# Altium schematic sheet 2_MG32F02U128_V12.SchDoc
size 388 x 266 mm; PageSetup: Record=PageOptions|CenterHorizontal=True|CenterVertical=True|PrintScale=0.73|XCorrection=1.00|YCorrection=1.00|PrintKind=1|BorderSize=5000000|LeftOffset=0|BottomOffset=0|Orientation=2|PaperLength=1000|PaperWidth=1000|Scale=100|PaperSource=7|PrintQuality=-4|MediaType=1|DitherType=10|PaperKind=A4 (210 x 297 mm)|PrintScaleMode=1
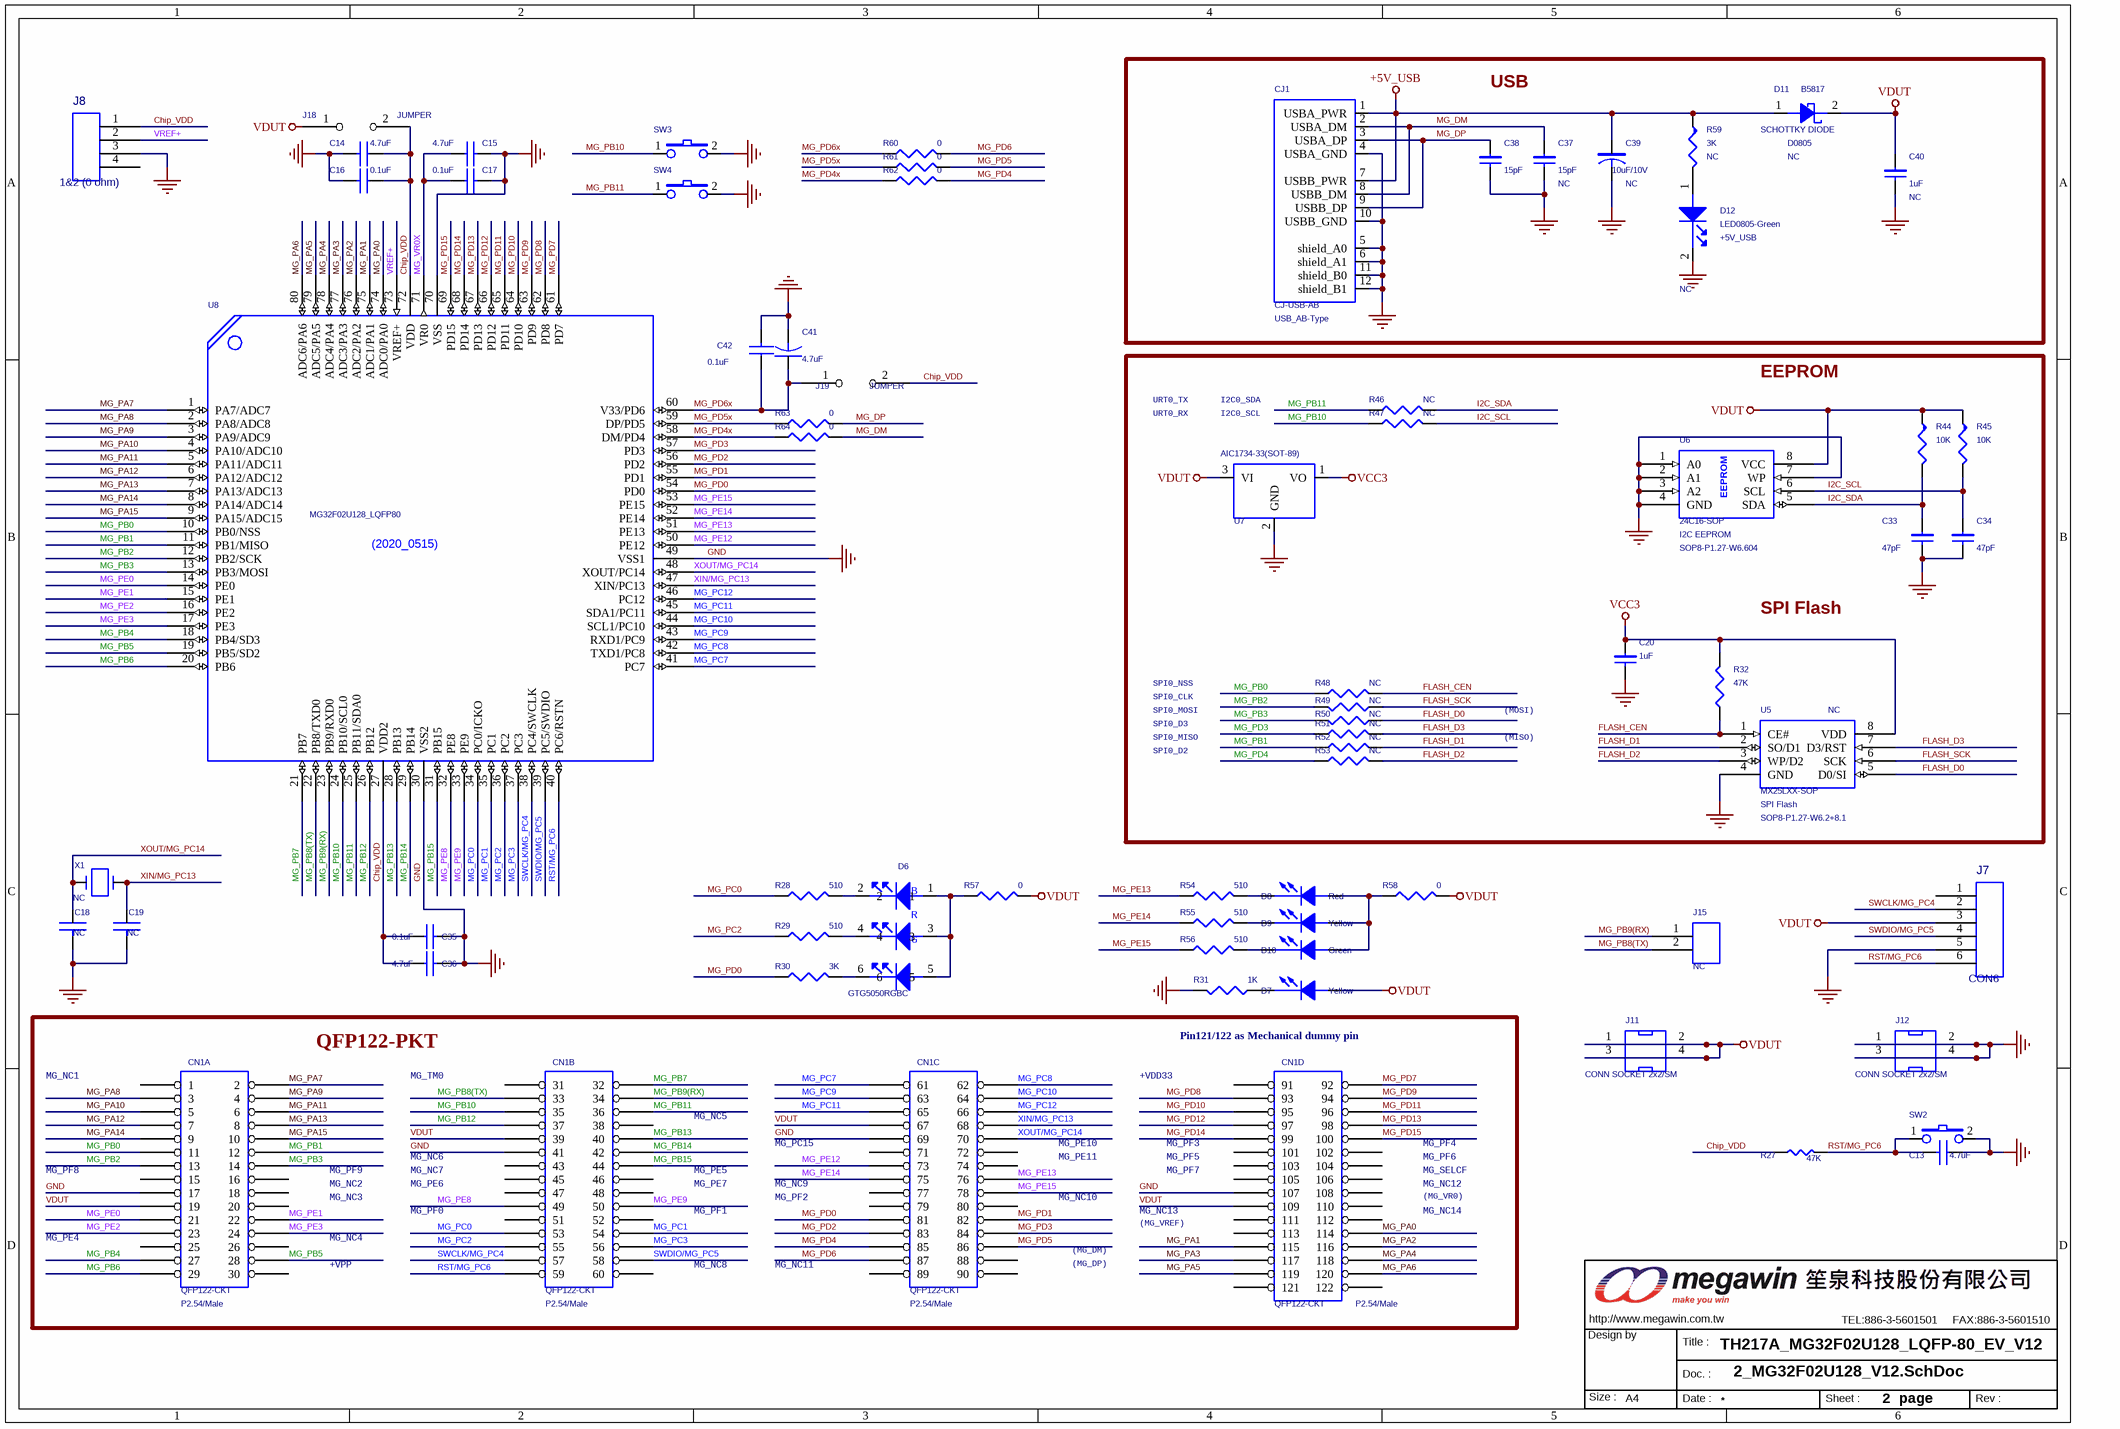
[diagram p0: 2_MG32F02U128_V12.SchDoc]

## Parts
C13  4.7uF  [0805C]
C14  4.7uF  [0805C]
C15  4.7uF  [0805C]
C16  0.1uF  [0603C]
C17  0.1uF  [0603C]
C18  NC  [0603C]
C19  NC  [0603C]
C20  1uF  [0603C]
C33  47pF  [0603C]
C34  47pF  [0603C]
C35  0.1uF  [0603C]
C36  4.7uF  [0805C]
C37  15pF  Assembly: NC  [0603C]
C38  15pF  [0603C]
C39  10uF/10V  Assembly: NC  [0805C]
C40  1uF  Assembly: NC  [0603C]
C41  4.7uF  [0805C]
C42  0.1uF  [0603C]
CJ1  CJ-USB-AB  Package: USB_AB-Type  [CON_USB-AB]
CN1  QFP122-CKT  Package: P2.54/Male  [QFP122-P2.54-CKT]  (parts A,B,C,D of 4)
D6  GTG5050RGBC  [LED6P_RGB_SMD_50X50]
D7  Yellow  [0805D]
D8  Red  [LED38+0805]
D9  Yellow  [LED38+0805]
D10  Green  [LED38+0805]
D11  B5817  Package: D0805  Function: SCHOTTKY DIODE  Assembly: NC  [D5817_SMD_1]
D12  LED0805-Green  Assembly: NC  Function: +5V_USB  [LED-0805]
J7  CON6  [PS6P254]
J8  1&2 (0 ohm)  [PS4P254]
J11  CONN SOCKET 2x2/SM  [PS2X2P254]
J12  CONN SOCKET 2x2/SM  [PS2X2P254]
J15  NC  [PS2P254]
J18  JUMPER  [PS2P254]
J19  JUMPER  [PS2P254]
MW1  OrgAddr3: TEL:886-3-5601501     FAX:886-3-5601510  [MEGAWIN_3.4]  (hidden comment: MW-A4)  (graphical)
R27  47K  [0603R]
R28  510  [0603R]
R29  510  [0603R]
R30  3K  [0603R]
R31  1K  [0603R]
R32  47K  [0603R]
R44  10K  [0603R]
R45  10K  [0603R]
R46  NC  [PS2p254+0603]
R47  NC  [PS2p254+0603]
R48  NC  [PS2p254+0603]
R49  NC  [PS2p254+0603]
R50  NC  [PS2p254+0603]
R51  NC  [PS2p254+0603]
R52  NC  [PS2p254+0603]
R53  NC  [PS2p254+0603]
R54  510  [0603R]
R55  510  [0603R]
R56  510  [0603R]
R57  0  [PS2p254+0603]
R58  0  [PS2p254+0603]
R59  3K  Assembly: NC  [0603R]
R60  0  [0603R]
R61  0  [0603R]
R62  0  [0603R]
R63  0  [0603R]
R64  0  [0603R]
SW2  SW TACT-SPST  [SW_T_2P]  (value not drawn)
SW3  SW TACT-SPST  [SW_T_2P]  (value not drawn)
SW4  SW TACT-SPST  [SW_T_2P]  (value not drawn)
U5  MX25LXX-SOP  Function: SPI Flash  Assembly: NC  Package: SOP8-P1.27-W6.2+8.1  [SO8_208P127]
U6  24C16-SOP  Function: I2C EEPROM  Package: SOP8-P1.27-W6.604  [SO8_150P127]
U7  AIC1734-33(SOT-89)  [SOT89]
U8  MG32F02U128_LQFP80  [QFP80-P0.4-Z12X12]
X1  NC  [X49U]

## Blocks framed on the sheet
USB: C37-C40 CJ1 D11 D12 R59
QFP122-PKT: CN1

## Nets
+5V_USB: C39.1 CJ1.1(USBA_PWR) CJ1.7(USBB_PWR) D11.1(ANODE) R59.1
GND: C13.1 C14.2 C15.2 C16.2 C17.2 C18.2 C19.2 C20.2 C33.2 C34.2 C35.2 C36.2 C37.2 C38.2 C39.2 C40.2 C41.2 C42.2 CJ1.4(USBA_GND) CJ1.5(shield_A0) CJ1.6(shield_A1) CJ1.10(USBB_GND) CJ1.11(shield_B0) CJ1.12(shield_B1) CN1.17 CN1.41 CN1.69 CN1.107 D12.2(C) J7.5 J8.3 J12.1 J12.2 J12.3 J12.4 R31.1 SW2.2 SW3.2 SW4.2 U5.4(GND) U6.1(A0) U6.2(A1) U6.3(A2) U6.4(GND) U6.7(WP) U7.2(GND) U8.30(VSS2) U8.49(VSS1) U8.70(VSS)  [also labelled GND_POWER]
VCC3: C20.1 R32.2 U5.8(VDD) U7.1(VO)
VDUT: C40.1 CN1.19 CN1.39 CN1.67 CN1.109 D7.1(ANODE) D11.2(CATHODE) J7.3 J11.1 J11.2 J11.3 J11.4 J18.1 R44.1 R45.1 R57.2 R58.2 U6.8(VCC) U7.3(VI)
Chip_VDD: C14.1 C16.1 C35.1 C36.1 J8.1 J18.2 J19.2 R27.1 U8.27(VDD2) U8.72(VDD)
FLASH_CEN: R32.1 R48.2 U5.1(CE#)
FLASH_D0: R50.1 U5.5(D0/SI)
FLASH_D1: R52.2 U5.2(SO/D1)
FLASH_D2: R53.2 U5.3(WP/D2)
FLASH_D3: R51.2 U5.7(D3/RST)
FLASH_SCK: R49.1 U5.6(SCK)
I2C_SCL: C34.1 R45.2 R47.2 U6.6(SCL)
I2C_SDA: C33.1 R44.2 R46.2 U6.5(SDA)
MG_DM: C37.1 CJ1.2(USBA_DM) CJ1.8(USBB_DM) R64.2
MG_DP: C38.1 CJ1.3(USBA_DP) CJ1.9(USBB_DP) R63.2
MG_PA0: CN1.114 U8.74(ADC0/PA0)
MG_PA1: CN1.115 U8.75(ADC1/PA1)
MG_PA2: CN1.116 U8.76(ADC2/PA2)
MG_PA3: CN1.117 U8.77(ADC3/PA3)
MG_PA4: CN1.118 U8.78(ADC4/PA4)
MG_PA5: CN1.119 U8.79(ADC5/PA5)
MG_PA6: CN1.120 U8.80(ADC6/PA6)
MG_PA7: CN1.2 U8.1(PA7/ADC7)
MG_PA8: CN1.3 U8.2(PA8/ADC8)
MG_PA9: CN1.4 U8.3(PA9/ADC9)
MG_PA10: CN1.5 U8.4(PA10/ADC10)
MG_PA11: CN1.6 U8.5(PA11/ADC11)
MG_PA12: CN1.7 U8.6(PA12/ADC12)
MG_PA13: CN1.8 U8.7(PA13/ADC13)
MG_PA14: CN1.9 U8.8(PA14/ADC14)
MG_PA15: CN1.10 U8.9(PA15/ADC15)
MG_PB0: CN1.11 R48.1 U8.10(PB0/NSS)
MG_PB1: CN1.12 R52.1 U8.11(PB1/MISO)
MG_PB2: CN1.13 R49.2 U8.12(PB2/SCK)
MG_PB3: CN1.14 R50.2 U8.13(PB3/MOSI)
MG_PB4: CN1.27 U8.18(PB4/SD3)
MG_PB5: CN1.28 U8.19(PB5/SD2)
MG_PB6: CN1.29 U8.20(PB6)
MG_PB7: CN1.32 U8.21(PB7)
MG_PB8(TX): CN1.33 J15.2 U8.22(PB8/TXD0)
MG_PB9(RX): CN1.34 J15.1 U8.23(PB9/RXD0)
MG_PB10: CN1.35 R47.1 SW3.1 U8.24(PB10/SCL0)
MG_PB11: CN1.36 R46.1 SW4.1 U8.25(PB11/SDA0)
MG_PB12: CN1.37 U8.26(PB12)
MG_PB13: CN1.40 U8.28(PB13)
MG_PB14: CN1.42 U8.29(PB14)
MG_PB15: CN1.44 U8.31(PB15)
MG_PC0: CN1.53 R28.1 U8.34(PC0/ICKO)
MG_PC1: CN1.54 U8.35(PC1)
MG_PC2: CN1.55 R29.1 U8.36(PC2)
MG_PC3: CN1.56 U8.37(PC3)
MG_PC7: CN1.61 U8.41(PC7)
MG_PC8: CN1.62 U8.42(TXD1/PC8)
MG_PC9: CN1.63 U8.43(RXD1/PC9)
MG_PC10: CN1.64 U8.44(SCL1/PC10)
MG_PC11: CN1.65 U8.45(SDA1/PC11)
MG_PC12: CN1.66 U8.46(PC12)
MG_PD0: CN1.81 R30.1 U8.54(PD0)
MG_PD1: CN1.82 U8.55(PD1)
MG_PD2: CN1.83 U8.56(PD2)
MG_PD3: CN1.84 R51.1 U8.57(PD3)
MG_PD4: CN1.85 R53.1 R62.2
MG_PD4x: R62.1 R64.1 U8.58(DM/PD4)
MG_PD5: CN1.86 R61.2
MG_PD5x: R61.1 R63.1 U8.59(DP/PD5)
MG_PD6: CN1.87 R60.2
MG_PD6x: C41.1 C42.1 J19.1 R60.1 U8.60(V33/PD6)
MG_PD7: CN1.92 U8.61(PD7)
MG_PD8: CN1.93 U8.62(PD8)
MG_PD9: CN1.94 U8.63(PD9)
MG_PD10: CN1.95 U8.64(PD10)
MG_PD11: CN1.96 U8.65(PD11)
MG_PD12: CN1.97 U8.66(PD12)
MG_PD13: CN1.98 U8.67(PD13)
MG_PD14: CN1.99 U8.68(PD14)
MG_PD15: CN1.100 U8.69(PD15)
MG_PE0: CN1.21 U8.14(PE0)
MG_PE1: CN1.22 U8.15(PE1)
MG_PE2: CN1.23 U8.16(PE2)
MG_PE3: CN1.24 U8.17(PE3)
MG_PE8: CN1.49 U8.32(PE8)
MG_PE9: CN1.50 U8.33(PE9)
MG_PE12: CN1.73 U8.50(PE12)
MG_PE13: CN1.76 R54.1 U8.51(PE13)
MG_PE14: CN1.75 R55.1 U8.52(PE14)
MG_PE15: CN1.78 R56.1 U8.53(PE15)
MG_VR0X: C15.1 C17.1 U8.71(VR0)
RST/MG_PC6: C13.2 CN1.59 J7.6 R27.2 SW2.1 U8.40(PC6/RSTN)
SWCLK/MG_PC4: CN1.57 J7.2 U8.38(PC4/SWCLK)
SWDIO/MG_PC5: CN1.58 J7.4 U8.39(PC5/SWDIO)
VREF+: J8.2 U8.73(VREF+)
XIN/MG_PC13: C19.1 CN1.68 U8.47(XIN/PC13) X1.2
XOUT/MG_PC14: C18.1 CN1.70 U8.48(XOUT/PC14) X1.1
NetD6_1: D6.1 D6.3 D6.5 R57.1
NetD6_2: D6.2 R28.2
NetD6_4: D6.4 R29.2
NetD6_6: D6.6 R30.2
NetD7_2: D7.2(CATHODE) R31.2
NetD8_1: D8.1(ANODE) D9.1(ANODE) D10.1(ANODE) R58.1
NetD8_2: D8.2(CATHODE) R54.2
NetD9_2: D9.2(CATHODE) R55.2
NetD10_2: D10.2(CATHODE) R56.2
NetD12_1: D12.1(A) R59.2

Not connected (* = marked no-connect by the designer): CN1 1 15 16 18 20 25 26 30 31 38 43 45 46 47 48 51 52 60 71 72 74 77 79 80 88 89 90 91 101 102 103 104 105 106 108 110 111 112 113 121 122; J7 1; J8 4

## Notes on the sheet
- URT0_TX
- URT0_RX
- I2C0_SDA
- I2C0_SCL
- EEPROM
- SPI Flash
- SPI0_NSS
- SPI0_CLK
- SPI0_MOSI
- SPI0_MISO
- SPI0_D3
- SPI0_D2
- (MOSI)
- (MISO)
- Pin121/122 as Mechanical dummy pin
- MG_NC1
- MG_TM0
- +VDD33
- MG_PF8
- MG_PF9
- MG_NC6
- MG_NC7
- MG_NC5
- MG_PE5
- MG_PC15
- MG_PE10
- MG_PE11
- MG_PF3
- MG_PF5
- MG_PF7
- MG_PF4
- MG_PF6
- MG_SELCF
- MG_PE4
- MG_NC2
- MG_NC3
- MG_NC4
- MG_PF0
- MG_PE6
- MG_PF1
- MG_PE7
- MG_NC9
- MG_PF2
- MG_NC10
- MG_NC13
- (MG_VREF)
- MG_NC12
- MG_NC14
- (MG_VR0)
- +VPP
- MG_NC8
- MG_NC11
- (MG_DM)
- (MG_DP)
- TH217A_MG32F02U128_LQFP-80_EV_V12
- 2 page

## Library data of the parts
C13-C17 C35 C36 C42 = CAP NP_Dup1
C18 C19 = C NP_Dup1
C20 C33 C34 C37 C40 = CAP-NP
C38 = CAP-NP: Assembly: NC
C39 = CAP-POL
C41 = CAP
CJ1 = CJ-USB-AB: Function: USB Connector
CN1 = QFP122-CKT: CN1
D6 = LED_GTG5050RGBC
D7-D10 = LED_Dup1
D11 = DIODE-SCHOTTKY-2
D12 = LED
J7 = CON6_Dup1
J8 = CON4
J15 = CON2
MW1 = MW_A4_2
R27 = R_Dup4
R28-R32 R46-R58 R60-R64 = R_Dup5
R44 R45 R59 = R: 2ND PART FIELD: SMD_0805
U5 = ICM-25LXX
U6 = ICM-24CXX: 1ST PART FIELD: OSD Record Buffer; 2ND PART FIELD: SOP_8PIN; Assembly: NC
U7 = AIC1722-33
U8 = IC-MG32F02U128-LQFP80: SPLIT_INST: TRUE; SWAP_INFO: (S1+S2); OriginalSymbolOrigin: (0,0); Designator: A
X1 = CRYSTAL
